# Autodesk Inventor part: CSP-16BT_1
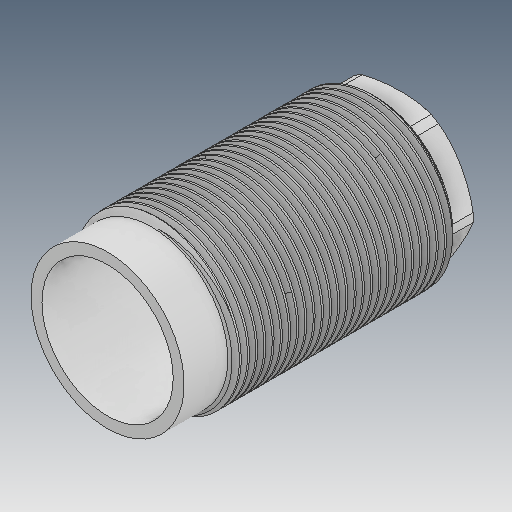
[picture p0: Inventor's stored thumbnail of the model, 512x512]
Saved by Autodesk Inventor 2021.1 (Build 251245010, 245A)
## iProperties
Created: 2021-06
Part Number: CSP-16BT_1
Material: Ogólny
Document SubType Name: Modeling
Designer: user
Density: 1 g/cm^3
Appearance: Domyślna
Author: user
Revision Number: ÈÎºÎ
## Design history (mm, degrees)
feature "ÊäÈë1"
node "Bryła1"
